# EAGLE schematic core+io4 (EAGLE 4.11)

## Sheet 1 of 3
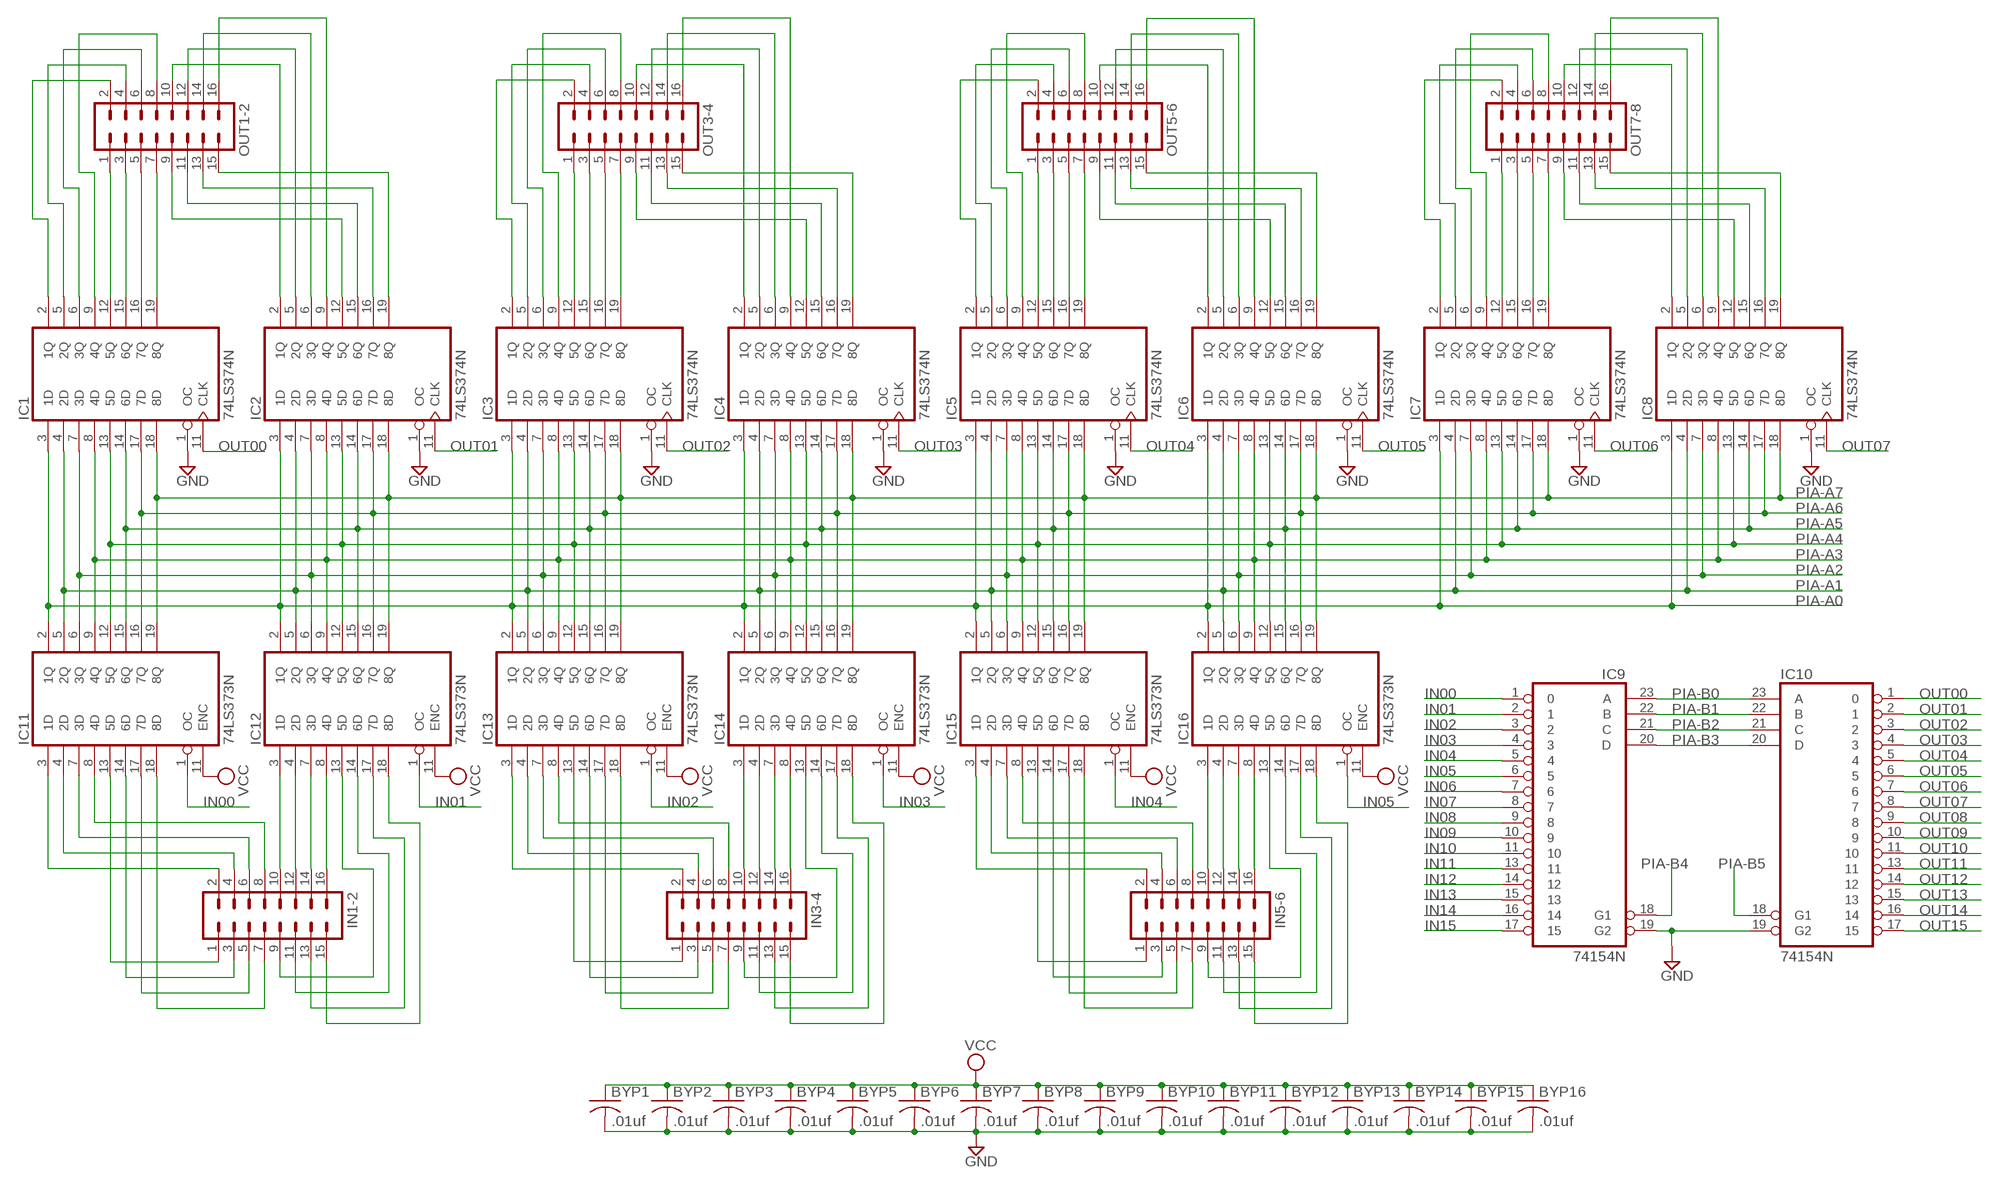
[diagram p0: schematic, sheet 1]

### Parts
BYP1  .01uf  C-US050-025X075  [C050-025X075]
BYP2  .01uf  C-US050-025X075  [C050-025X075]
BYP3  .01uf  C-US050-025X075  [C050-025X075]
BYP4  .01uf  C-US050-025X075  [C050-025X075]
BYP5  .01uf  C-US050-025X075  [C050-025X075]
BYP6  .01uf  C-US050-025X075  [C050-025X075]
BYP7  .01uf  C-US050-025X075  [C050-025X075]
BYP8  .01uf  C-US050-025X075  [C050-025X075]
BYP9  .01uf  C-US050-025X075  [C050-025X075]
BYP10  .01uf  C-US050-025X075  [C050-025X075]
BYP11  .01uf  C-US050-025X075  [C050-025X075]
BYP12  .01uf  C-US050-025X075  [C050-025X075]
BYP13  .01uf  C-US050-025X075  [C050-025X075]
BYP14  .01uf  C-US050-025X075  [C050-025X075]
BYP15  .01uf  C-US050-025X075  [C050-025X075]
BYP16  .01uf  C-US050-025X075  [C050-025X075]
IC1  74LS374N  [DIL20]
IC2  74LS374N  [DIL20]
IC3  74LS374N  [DIL20]
IC4  74LS374N  [DIL20]
IC5  74LS374N  [DIL20]
IC6  74LS374N  [DIL20]
IC7  74LS374N  [DIL20]
IC8  74LS374N  [DIL20]
IC9  74154N  [DIL24-6]
IC10  74154N  [DIL24-6]
IC11  74LS373N  [DIL20]
IC12  74LS373N  [DIL20]
IC13  74LS373N  [DIL20]
IC14  74LS373N  [DIL20]
IC15  74LS373N  [DIL20]
IC16  74LS373N  [DIL20]
IN1-2  MA08-2  [MA08-2]
IN3-4  MA08-2  [MA08-2]
IN5-6  MA08-2  [MA08-2]
OUT1-2  MA08-2  [MA08-2]
OUT3-4  MA08-2  [MA08-2]
OUT5-6  MA08-2  [MA08-2]
OUT7-8  MA08-2  [MA08-2]

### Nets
GND [Power]: BYP1.2 BYP2.2 BYP3.2 BYP4.2 BYP5.2 BYP6.2 BYP7.2 BYP8.2 BYP9.2 BYP10.2 BYP11.2 BYP12.2 BYP13.2 BYP14.2 BYP15.2 BYP16.2 IC1.1(OC) IC2.1(OC) IC3.1(OC) IC4.1(OC) IC5.1(OC) IC6.1(OC) IC7.1(OC) IC8.1(OC) IC9.19(G2) IC10.19(G2) ; also sheet 2,3
IN00: IC9.1 IC11.1(OC)
IN01: IC9.2 IC12.1(OC)
IN02: IC9.3 IC13.1(OC)
IN03: IC9.4 IC14.1(OC)
IN04: IC9.5 IC15.1(OC)
IN05: IC9.6 IC16.1(OC)
IN06: IC9.7
IN07: IC9.8
IN08: IC9.9
IN09: IC9.10
IN10: IC9.11
IN11: IC9.13
IN12: IC9.14
IN13: IC9.15
IN14: IC9.16
IN15: IC9.17
N$1: IC12.3(1D) IN1-2.10
N$2: IC12.4(2D) IN1-2.12
N$7: IC12.7(3D) IN1-2.14
N$8: IC12.8(4D) IN1-2.16
N$9: IC11.8(4D) IN1-2.8
N$10: IC11.7(3D) IN1-2.6
N$11: IC11.4(2D) IN1-2.4
N$12: IC11.3(1D) IN1-2.2
N$13: IC11.13(5D) IN1-2.1
N$14: IC11.14(6D) IN1-2.3
N$15: IC11.17(7D) IN1-2.5
N$16: IC11.18(8D) IN1-2.7
N$17: IC12.13(5D) IN1-2.9
N$18: IC12.14(6D) IN1-2.11
N$19: IC12.17(7D) IN1-2.13
N$20: IC12.18(8D) IN1-2.15
N$26: IC5.2(1Q) IC7.2(1Q) OUT5-6.2 OUT7-8.2
N$29: IC14.3(1D) IN3-4.10
N$30: IC14.4(2D) IN3-4.12
N$31: IC14.7(3D) IN3-4.14
N$32: IC14.8(4D) IN3-4.16
N$33: IC3.12(5Q) OUT3-4.1
N$34: IC3.15(6Q) OUT3-4.3
N$35: IC3.16(7Q) OUT3-4.5
N$36: IC3.19(8Q) OUT3-4.7
N$37: IC13.3(1D) IN3-4.2
N$38: IC13.4(2D) IN3-4.4
N$39: IC13.7(3D) IN3-4.6
N$40: IC13.8(4D) IN3-4.8
N$41: IC14.13(5D) IN3-4.9
N$42: IC14.14(6D) IN3-4.11
N$43: IC14.17(7D) IN3-4.13
N$44: IC14.18(8D) IN3-4.15
N$45: IC13.13(5D) IN3-4.1
N$46: IC13.14(6D) IN3-4.3
N$47: IC13.17(7D) IN3-4.5
N$48: IC13.18(8D) IN3-4.7
N$49: IC3.5(2Q) OUT3-4.4
N$50: IC3.6(3Q) OUT3-4.6
N$51: IC3.2(1Q) OUT3-4.2
N$52: IC3.9(4Q) OUT3-4.8
N$53: IC1.12(5Q) OUT1-2.1
N$54: IC1.15(6Q) OUT1-2.3
N$55: IC1.16(7Q) OUT1-2.5
N$56: IC1.19(8Q) OUT1-2.7
N$57: IC1.2(1Q) OUT1-2.2
N$58: IC1.5(2Q) OUT1-2.4
N$59: IC1.6(3Q) OUT1-2.6
N$60: IC1.9(4Q) OUT1-2.8
N$61: IC2.19(8Q) OUT1-2.15
N$62: IC2.16(7Q) OUT1-2.13
N$63: IC2.15(6Q) OUT1-2.11
N$64: IC2.12(5Q) OUT1-2.9
N$65: IC2.2(1Q) OUT1-2.10
N$66: IC2.5(2Q) OUT1-2.12
N$67: IC2.6(3Q) OUT1-2.14
N$68: IC2.9(4Q) OUT1-2.16
N$69: IC4.2(1Q) OUT3-4.10
N$70: IC4.5(2Q) OUT3-4.12
N$71: IC4.6(3Q) OUT3-4.14
N$72: IC4.9(4Q) OUT3-4.16
N$73: IC4.19(8Q) OUT3-4.15
N$74: IC4.16(7Q) OUT3-4.13
N$75: IC4.15(6Q) OUT3-4.11
N$76: IC4.12(5Q) OUT3-4.9
N$77: IC16.3(1D) IN5-6.10
N$78: IC16.4(2D) IN5-6.12
N$79: IC16.7(3D) IN5-6.14
N$80: IC16.8(4D) IN5-6.16
N$81: IC5.12(5Q) OUT5-6.1
N$82: IC5.15(6Q) OUT5-6.3
N$83: IC5.16(7Q) OUT5-6.5
N$84: IC5.19(8Q) OUT5-6.7
N$85: IC7.12(5Q) OUT7-8.1
N$86: IC7.15(6Q) OUT7-8.3
N$87: IC7.16(7Q) OUT7-8.5
N$88: IC7.19(8Q) OUT7-8.7
N$89: IC5.5(2Q) OUT5-6.4
N$90: IC5.6(3Q) OUT5-6.6
N$91: IC5.9(4Q) OUT5-6.8
N$92: IC6.12(5Q) OUT5-6.9
N$93: IC6.15(6Q) OUT5-6.11
N$95: IC6.16(7Q) OUT5-6.13
N$96: IC6.19(8Q) OUT5-6.15
N$97: IC6.2(1Q) OUT5-6.10
N$98: IC6.5(2Q) OUT5-6.12
N$99: IC6.6(3Q) OUT5-6.14
N$100: IC6.9(4Q) OUT5-6.16
N$101: IC15.3(1D) IN5-6.2
N$102: IC15.4(2D) IN5-6.4
N$103: IC15.7(3D) IN5-6.6
N$104: IC15.8(4D) IN5-6.8
N$105: IC16.13(5D) IN5-6.9
N$106: IC16.14(6D) IN5-6.11
N$107: IC16.17(7D) IN5-6.13
N$108: IC16.18(8D) IN5-6.15
N$109: IC15.13(5D) IN5-6.1
N$110: IC15.14(6D) IN5-6.3
N$111: IC15.17(7D) IN5-6.5
N$112: IC15.18(8D) IN5-6.7
N$113: IC8.19(8Q) OUT7-8.15
N$114: IC8.16(7Q) OUT7-8.13
N$115: IC8.15(6Q) OUT7-8.11
N$116: IC8.12(5Q) OUT7-8.9
N$117: IC8.2(1Q) OUT7-8.10
N$118: IC8.5(2Q) OUT7-8.12
N$119: IC8.6(3Q) OUT7-8.14
N$120: IC8.9(4Q) OUT7-8.16
N$121: IC7.9(4Q) OUT7-8.8
N$122: IC7.6(3Q) OUT7-8.6
N$123: IC7.5(2Q) OUT7-8.4
OUT00: IC1.11(CLK) IC10.1
OUT01: IC2.11(CLK) IC10.2
OUT02: IC3.11(CLK) IC10.3
OUT03: IC4.11(CLK) IC10.4
OUT04: IC5.11(CLK) IC10.5
OUT05: IC6.11(CLK) IC10.6
OUT06: IC7.11(CLK) IC10.7
OUT07: IC8.11(CLK) IC10.8
OUT08: IC10.9
OUT09: IC10.10
OUT10: IC10.11
OUT11: IC10.13
OUT12: IC10.14
OUT13: IC10.15
OUT14: IC10.16
OUT15: IC10.17
PIA-A0: IC1.3(1D) IC2.3(1D) IC3.3(1D) IC4.3(1D) IC5.3(1D) IC6.3(1D) IC7.3(1D) IC8.3(1D) IC11.2(1Q) IC12.2(1Q) IC13.2(1Q) IC14.2(1Q) IC15.2(1Q) IC16.2(1Q) ; also sheet 2,3
PIA-A1: IC1.4(2D) IC2.4(2D) IC3.4(2D) IC4.4(2D) IC5.4(2D) IC6.4(2D) IC7.4(2D) IC8.4(2D) IC11.5(2Q) IC12.5(2Q) IC13.5(2Q) IC14.5(2Q) IC15.5(2Q) IC16.5(2Q) ; also sheet 2,3
PIA-A2: IC1.7(3D) IC2.7(3D) IC3.7(3D) IC4.7(3D) IC5.7(3D) IC6.7(3D) IC7.7(3D) IC8.7(3D) IC11.6(3Q) IC12.6(3Q) IC13.6(3Q) IC14.6(3Q) IC15.6(3Q) IC16.6(3Q) ; also sheet 2,3
PIA-A3: IC1.8(4D) IC2.8(4D) IC3.8(4D) IC4.8(4D) IC5.8(4D) IC6.8(4D) IC7.8(4D) IC8.8(4D) IC11.9(4Q) IC12.9(4Q) IC13.9(4Q) IC14.9(4Q) IC15.9(4Q) IC16.9(4Q) ; also sheet 2,3
PIA-A4: IC1.13(5D) IC2.13(5D) IC3.13(5D) IC4.13(5D) IC5.13(5D) IC6.13(5D) IC7.13(5D) IC8.13(5D) IC11.12(5Q) IC12.12(5Q) IC13.12(5Q) IC14.12(5Q) IC15.12(5Q) IC16.12(5Q) ; also sheet 2,3
PIA-A5: IC1.14(6D) IC2.14(6D) IC3.14(6D) IC4.14(6D) IC5.14(6D) IC6.14(6D) IC7.14(6D) IC8.14(6D) IC11.15(6Q) IC12.15(6Q) IC13.15(6Q) IC14.15(6Q) IC15.15(6Q) IC16.15(6Q) ; also sheet 2,3
PIA-A6: IC1.17(7D) IC2.17(7D) IC3.17(7D) IC4.17(7D) IC5.17(7D) IC6.17(7D) IC7.17(7D) IC8.17(7D) IC11.16(7Q) IC12.16(7Q) IC13.16(7Q) IC14.16(7Q) IC15.16(7Q) IC16.16(7Q) ; also sheet 2,3
PIA-A7: IC1.18(8D) IC2.18(8D) IC3.18(8D) IC4.18(8D) IC5.18(8D) IC6.18(8D) IC7.18(8D) IC8.18(8D) IC11.19(8Q) IC12.19(8Q) IC13.19(8Q) IC14.19(8Q) IC15.19(8Q) IC16.19(8Q) ; also sheet 2,3
PIA-B0: IC9.23(A) IC10.23(A) ; also sheet 2,3
PIA-B1: IC9.22(B) IC10.22(B) ; also sheet 2,3
PIA-B2: IC9.21(C) IC10.21(C) ; also sheet 2,3
PIA-B3: IC9.20(D) IC10.20(D) ; also sheet 2,3
PIA-B4: IC9.18(G1) ; also sheet 2,3
PIA-B5: IC10.18(G1) ; also sheet 2,3
VCC [Power]: BYP1.1 BYP2.1 BYP3.1 BYP4.1 BYP5.1 BYP6.1 BYP7.1 BYP8.1 BYP9.1 BYP10.1 BYP11.1 BYP12.1 BYP13.1 BYP14.1 BYP15.1 BYP16.1 IC11.11(ENC) IC12.11(ENC) IC13.11(ENC) IC14.11(ENC) IC15.11(ENC) IC16.11(ENC) ; also sheet 2,3

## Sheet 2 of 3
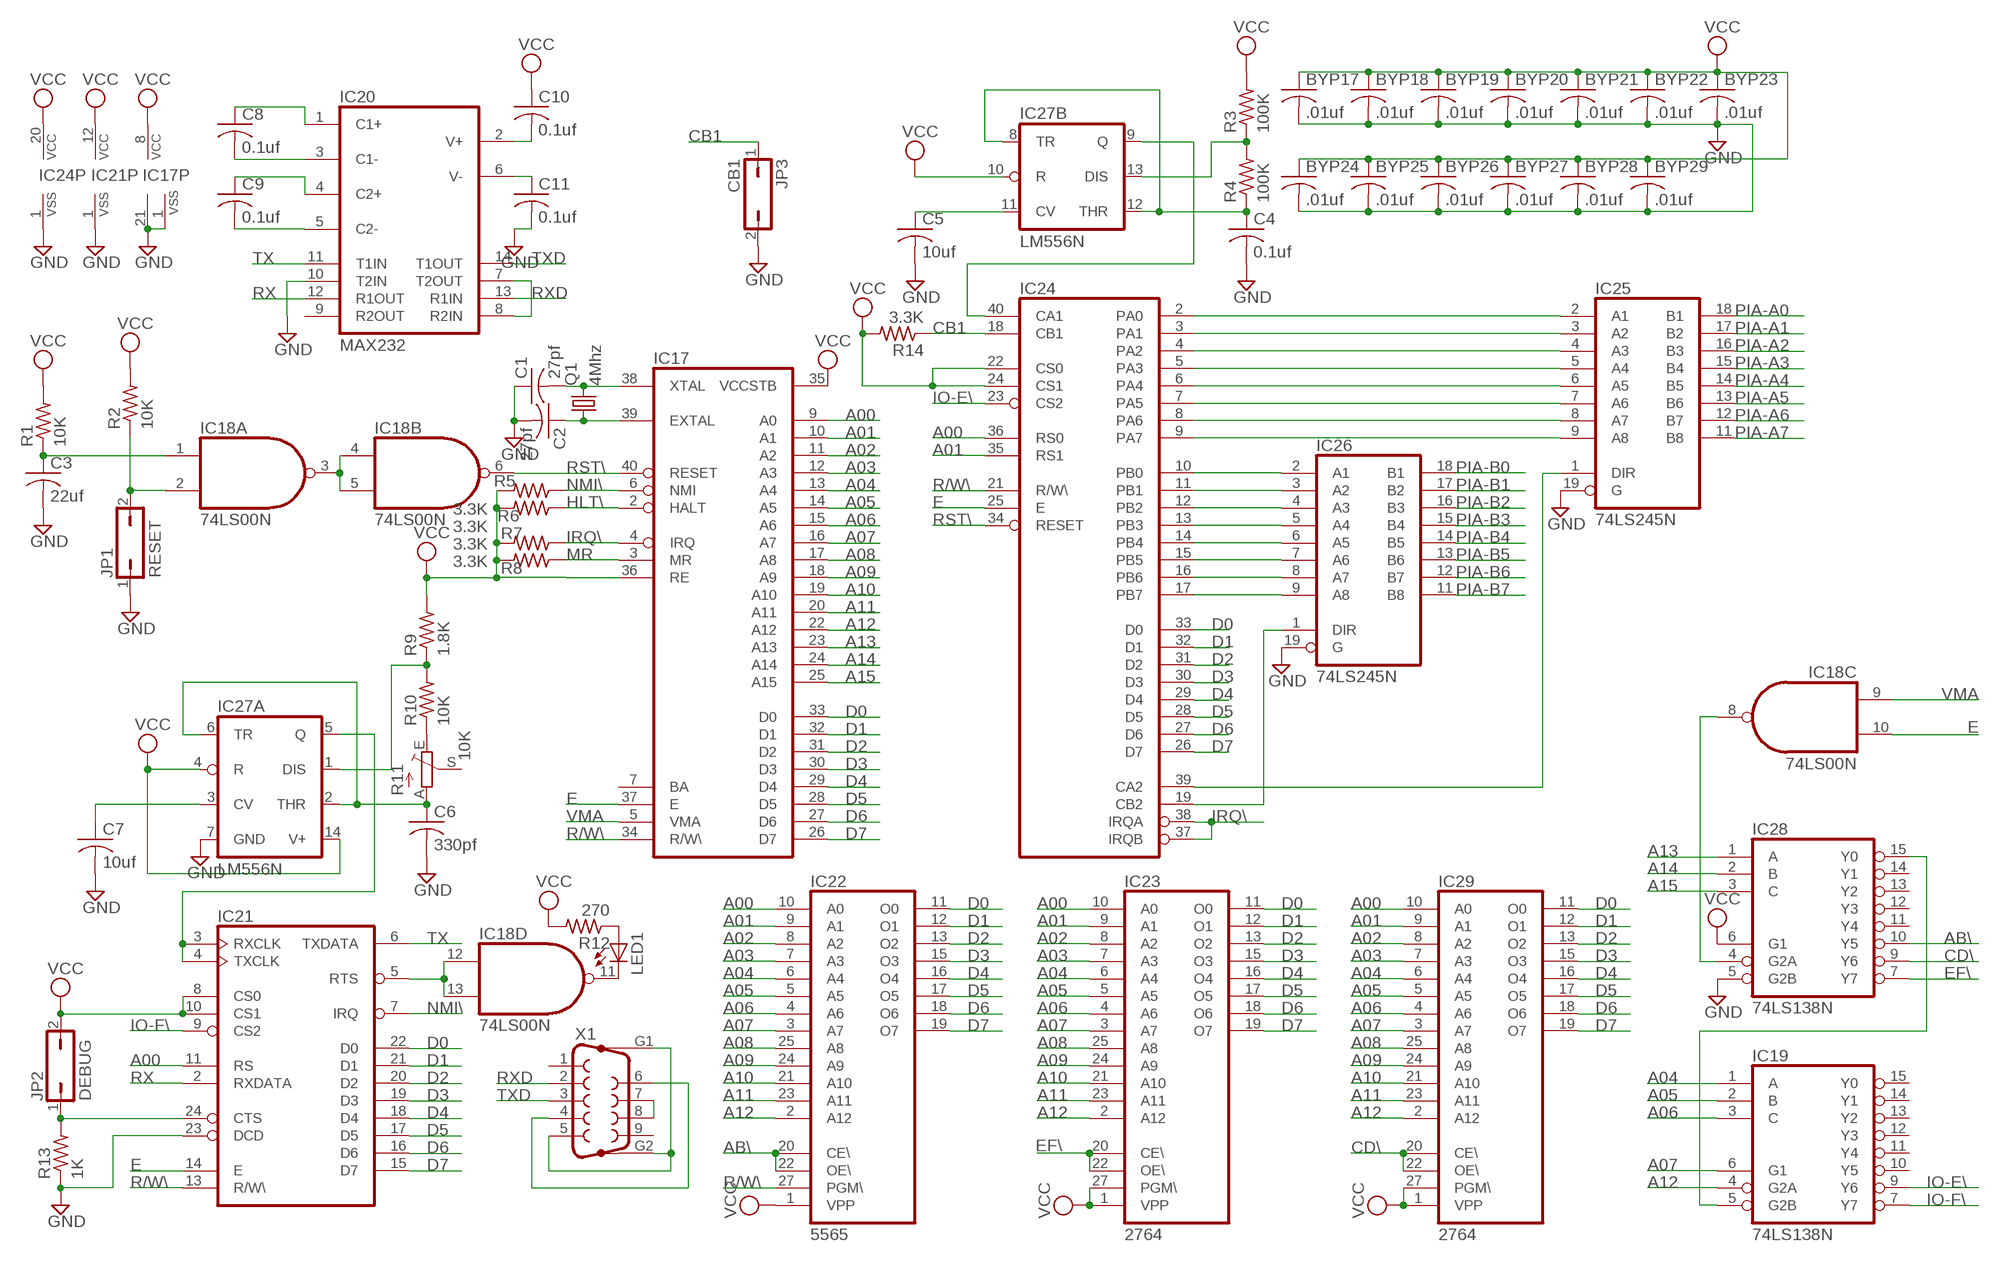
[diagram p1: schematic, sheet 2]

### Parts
BYP17  .01uf  C-US050-025X075  [C050-025X075]
BYP18  .01uf  C-US050-025X075  [C050-025X075]
BYP19  .01uf  C-US050-025X075  [C050-025X075]
BYP20  .01uf  C-US050-025X075  [C050-025X075]
BYP21  .01uf  C-US050-025X075  [C050-025X075]
BYP22  .01uf  C-US050-025X075  [C050-025X075]
BYP23  .01uf  C-US050-025X075  [C050-025X075]
BYP24  .01uf  C-US050-025X075  [C050-025X075]
BYP25  .01uf  C-US050-025X075  [C050-025X075]
BYP26  .01uf  C-US050-025X075  [C050-025X075]
BYP27  .01uf  C-US050-025X075  [C050-025X075]
BYP28  .01uf  C-US050-025X075  [C050-025X075]
BYP29  .01uf  C-US050-025X075  [C050-025X075]
C1  27pf  C-US050-025X075  [C050-025X075]
C2  27pf  C-US050-025X075  [C050-025X075]
C3  22uf  C-US102-043X133  [C102-043X133]
C4  0.1uf  C-US050-025X075  [C050-025X075]
C5  10uf  C-US050-025X075  [C050-025X075]
C6  330pf  C-US050-025X075  [C050-025X075]
C7  10uf  C-US050-025X075  [C050-025X075]
C8  0.1uf  C-US050-025X075  [C050-025X075]
C9  0.1uf  C-US050-025X075  [C050-025X075]
C10  0.1uf  C-US050-025X075  [C050-025X075]
C11  0.1uf  C-US050-025X075  [C050-025X075]
IC17  6802  [DIL40]
IC18  74LS00N  [DIL14]
IC19  74LS138N  [DIL16]
IC20  MAX232  [DIL16]
IC21  6850  [DIL24]
IC22  5565  2764  [DIL28]
IC23  2764  [DIL28]
IC24  6821  [DIL40]
IC25  74LS245N  [DIL20]
IC26  74LS245N  [DIL20]
IC27  LM556N  [DIL14]
IC28  74LS138N  [DIL16]
IC29  2764  [DIL28]
JP1  RESET  JP1Q  [JP1]
JP2  DEBUG  JP1Q  [JP1]
JP3  CB1  JP1Q  [JP1]
LED1  LED3MM  [LED3MM]
Q1  4Mhz  CRYTALHC18U-V  [HC18U-V]
R1  10K  R-US_0207/7  [0207/7]
R2  10K  R-US_0207/7  [0207/7]
R3  100K  R-US_0207/7  [0207/7]
R4  100K  R-US_0207/7  [0207/7]
R5  3.3K  R-US_0207/7  [0207/7]
R6  3.3K  R-US_0207/7  [0207/7]
R7  3.3K  R-US_0207/7  [0207/7]
R8  3.3K  R-US_0207/7  [0207/7]
R9  1.8K  R-US_0207/7  [0207/7]
R10  10K  R-US_0207/7  [0207/7]
R11  10K  TRIM_EU-B90P  [SP19L]
R12  270  R-US_0207/7  [0207/7]
R13  1K  R-US_0207/7  [0207/7]
R14  3.3K  R-US_0207/7  [0207/7]
X1  F09HP  [F09HP]

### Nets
A00: IC17.9(A0) IC21.11(RS) IC22.10(A0) IC23.10(A0) IC24.36(RS0) IC29.10(A0)
A01: IC17.10(A1) IC22.9(A1) IC23.9(A1) IC24.35(RS1) IC29.9(A1)
A02: IC17.11(A2) IC22.8(A2) IC23.8(A2) IC29.8(A2)
A03: IC17.12(A3) IC22.7(A3) IC23.7(A3) IC29.7(A3)
A04: IC17.13(A4) IC19.1(A) IC22.6(A4) IC23.6(A4) IC29.6(A4)
A05: IC17.14(A5) IC19.2(B) IC22.5(A5) IC23.5(A5) IC29.5(A5)
A06: IC17.15(A6) IC19.3(C) IC22.4(A6) IC23.4(A6) IC29.4(A6)
A07: IC17.16(A7) IC19.6(G1) IC22.3(A7) IC23.3(A7) IC29.3(A7)
A08: IC17.17(A8) IC22.25(A8) IC23.25(A8) IC29.25(A8)
A09: IC17.18(A9) IC22.24(A9) IC23.24(A9) IC29.24(A9)
A10: IC17.19(A10) IC22.21(A10) IC23.21(A10) IC29.21(A10)
A11: IC17.20(A11) IC22.23(A11) IC23.23(A11) IC29.23(A11)
A12: IC17.22(A12) IC19.4(G2A) IC22.2(A12) IC23.2(A12) IC29.2(A12)
A13: IC17.23(A13) IC28.1(A)
A14: IC17.24(A14) IC28.2(B)
A15: IC17.25(A15) IC28.3(C)
AB\: IC22.20(CE\) IC22.22(OE\) IC28.10(Y5)
CB1: IC24.18(CB1) JP3.1 R14.1
CD\: IC28.9(Y6) IC29.20(CE\) IC29.22(OE\)
D0: IC17.33(D0) IC21.22(D0) IC22.11(O0) IC23.11(O0) IC24.33(D0) IC29.11(O0)
D1: IC17.32(D1) IC21.21(D1) IC22.12(O1) IC23.12(O1) IC24.32(D1) IC29.12(O1)
D2: IC17.31(D2) IC21.20(D2) IC22.13(O2) IC23.13(O2) IC24.31(D2) IC29.13(O2)
D3: IC17.30(D3) IC21.19(D3) IC22.15(O3) IC23.15(O3) IC24.30(D3) IC29.15(O3)
D4: IC17.29(D4) IC21.18(D4) IC22.16(O4) IC23.16(O4) IC24.29(D4) IC29.16(O4)
D5: IC17.28(D5) IC21.17(D5) IC22.17(O5) IC23.17(O5) IC24.28(D5) IC29.17(O5)
D6: IC17.27(D6) IC21.16(D6) IC22.18(O6) IC23.18(O6) IC24.27(D6) IC29.18(O6)
D7: IC17.26(D7) IC21.15(D7) IC22.19(O7) IC23.19(O7) IC24.26(D7) IC29.19(O7)
E: IC17.37(E) IC18.10(C:I1) IC21.14(E) IC24.25(E)
EF\: IC23.20(CE\) IC23.22(OE\) IC28.7(Y7)
GND [Power]: BYP17.2 BYP18.2 BYP19.2 BYP20.2 BYP21.2 BYP22.2 BYP23.2 BYP24.2 BYP25.2 BYP26.2 BYP27.2 BYP28.2 BYP29.2 C1.1 C2.2 C3.2 C4.2 C5.2 C6.2 C7.2 C11.2 IC17.1(VSS) IC17.21(VSS) IC20.10(T2IN) IC21.1(VSS) IC21.23(DCD) IC24.1(VSS) IC25.19(G) IC26.19(G) IC27.7(A:GND) IC28.5(G2B) JP1.1 JP3.2 R13.1 ; also sheet 1,3
HLT\: IC17.2(HALT) R5.1
IO-E\: IC19.9(Y6) IC24.23(CS2)
IO-F\: IC19.7(Y7) IC21.9(CS2)
IRQ\: IC17.4(IRQ) IC24.37(IRQB) IC24.38(IRQA) R7.1
MR: IC17.3(MR) R8.1
N$3: C2.1 IC17.39(EXTAL) Q1.1
N$4: C1.2 IC17.38(XTAL) Q1.2
N$5: IC24.2(PA0) IC25.2(A1)
N$6: IC18.3(A:O) IC18.4(B:I0) IC18.5(B:I1)
N$21: C3.1 IC18.1(A:I0) R1.1
N$22: IC18.2(A:I1) JP1.2 R2.1
N$23: IC21.3(RXCLK) IC21.4(TXCLK) IC27.5(A:Q)
N$24: IC24.10(PB0) IC26.2(A1)
N$25: IC24.11(PB1) IC26.3(A2)
N$27: C6.1 IC27.2(A:THR) IC27.6(A:TR) R11.A
N$28: IC27.1(A:DIS) R9.1 R10.2
N$94: IC24.12(PB2) IC26.4(A3)
N$124: IC24.13(PB3) IC26.5(A4)
N$125: IC24.14(PB4) IC26.6(A5)
N$126: IC24.15(PB5) IC26.7(A6)
N$127: IC24.16(PB6) IC26.8(A7)
N$128: IC24.17(PB7) IC26.9(A8)
N$129: IC24.3(PA1) IC25.3(A2)
N$130: IC24.4(PA2) IC25.4(A3)
N$131: IC24.5(PA3) IC25.5(A4)
N$132: IC24.6(PA4) IC25.6(A5)
N$133: IC24.7(PA5) IC25.7(A6)
N$134: IC24.8(PA6) IC25.8(A7)
N$135: IC24.9(PA7) IC25.9(A8)
N$136: IC24.19(CB2) IC26.1(DIR)
N$137: IC24.39(CA2) IC25.1(DIR)
N$138: IC24.40(CA1) IC27.9(B:Q)
N$140: C4.1 IC27.8(B:TR) IC27.12(B:THR) R4.1
N$141: IC27.13(B:DIS) R3.1 R4.2
N$142: C5.1 IC27.11(B:CV)
N$143: R10.1 R11.E
N$144: X1.4 X1.6
N$145: X1.7 X1.8
N$146: X1.5 X1.G1 X1.G2
N$147: IC18.12(D:I0) IC18.13(D:I1) IC21.5(RTS)
N$148: IC18.11(D:O) LED1.K(C)
N$149: LED1.A R12.1
N$150: IC21.24(CTS) JP2.1 R13.2
N$151: IC18.8(C:O) IC28.4(G2A)
N$152: IC19.5(G2B) IC28.15(Y0)
N$153: IC20.7(T2OUT) IC20.8(R2IN)
N$154: C7.1 IC27.3(A:CV)
N$155: C9.2 IC20.5(C2-)
N$156: C9.1 IC20.4(C2+)
N$157: C8.2 IC20.3(C1-)
N$158: C8.1 IC20.1(C1+)
N$159: C11.1 IC20.6(V-)
N$160: C10.2 IC20.2(V+)
NMI\: IC17.6(NMI) IC21.7(IRQ) R6.1
PIA-A0: IC25.18(B1) ; also sheet 1,3
PIA-A1: IC25.17(B2) ; also sheet 1,3
PIA-A2: IC25.16(B3) ; also sheet 1,3
PIA-A3: IC25.15(B4) ; also sheet 1,3
PIA-A4: IC25.14(B5) ; also sheet 1,3
PIA-A5: IC25.13(B6) ; also sheet 1,3
PIA-A6: IC25.12(B7) ; also sheet 1,3
PIA-A7: IC25.11(B8) ; also sheet 1,3
PIA-B0: IC26.18(B1) ; also sheet 1,3
PIA-B1: IC26.17(B2) ; also sheet 1,3
PIA-B2: IC26.16(B3) ; also sheet 1,3
PIA-B3: IC26.15(B4) ; also sheet 1,3
PIA-B4: IC26.14(B5) ; also sheet 1,3
PIA-B5: IC26.13(B6) ; also sheet 1,3
PIA-B6: IC26.12(B7) ; also sheet 3
PIA-B7: IC26.11(B8) ; also sheet 3
R/W\: IC17.34(R/W\) IC21.13(R/W\) IC22.27(PGM\) IC24.21(R/W\)
RST\: IC17.40(RESET) IC18.6(B:O) IC24.34(RESET)
RX: IC20.12(R1OUT) IC21.2(RXDATA)
RXD: IC20.13(R1IN) X1.2
TX: IC20.11(T1IN) IC21.6(TXDATA)
TXD: IC20.14(T1OUT) X1.3
VCC [Power]: BYP17.1 BYP18.1 BYP19.1 BYP20.1 BYP21.1 BYP22.1 BYP23.1 BYP24.1 BYP25.1 BYP26.1 BYP27.1 BYP28.1 BYP29.1 C10.1 IC17.8(VCC) IC17.35(VCCSTB) IC17.36(RE) IC21.8(CS0) IC21.10(CS1) IC21.12(VCC) IC22.1(VPP) IC23.1(VPP) IC23.27(PGM\) IC24.20(VCC) IC24.22(CS0) IC24.24(CS1) IC27.4(A:R) IC27.10(B:R) IC27.14(A:V+) IC28.6(G1) IC29.1(VPP) IC29.27(PGM\) JP2.2 R1.2 R2.2 R3.2 R5.2 R6.2 R7.2 R8.2 R9.2 R12.2 R14.2 ; also sheet 1,3
VMA: IC17.5(VMA) IC18.9(C:I0)
Unconnected: IC17.7(BA) IC19.10(Y5) IC19.11(Y4) IC19.12(Y3) IC19.13(Y2) IC19.14(Y1) IC19.15(Y0) IC20.9(R2OUT) IC28.11(Y4) IC28.12(Y3) IC28.13(Y2) IC28.14(Y1) R11.S X1.1 X1.9

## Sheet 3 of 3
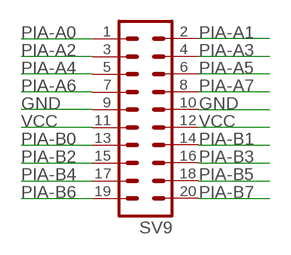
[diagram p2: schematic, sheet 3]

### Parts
SV9  MA10-2  [MA10-2]

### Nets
GND [Power]: SV9.9 SV9.10 ; also sheet 1,2
PIA-A0: SV9.1 ; also sheet 1,2
PIA-A1: SV9.2 ; also sheet 1,2
PIA-A2: SV9.3 ; also sheet 1,2
PIA-A3: SV9.4 ; also sheet 1,2
PIA-A4: SV9.5 ; also sheet 1,2
PIA-A5: SV9.6 ; also sheet 1,2
PIA-A6: SV9.7 ; also sheet 1,2
PIA-A7: SV9.8 ; also sheet 1,2
PIA-B0: SV9.13 ; also sheet 1,2
PIA-B1: SV9.14 ; also sheet 1,2
PIA-B2: SV9.15 ; also sheet 1,2
PIA-B3: SV9.16 ; also sheet 1,2
PIA-B4: SV9.17 ; also sheet 1,2
PIA-B5: SV9.18 ; also sheet 1,2
PIA-B6: SV9.19 ; also sheet 2
PIA-B7: SV9.20 ; also sheet 2
VCC [Power]: SV9.11 SV9.12 ; also sheet 1,2

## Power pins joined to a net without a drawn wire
GND: IC1.10(GND) IC2.10(GND) IC3.10(GND) IC4.10(GND) IC5.10(GND) IC6.10(GND) IC7.10(GND) IC8.10(GND) IC9.12(GND) IC10.12(GND) IC11.10(GND) IC12.10(GND) IC13.10(GND) IC14.10(GND) IC15.10(GND) IC16.10(GND) IC18.7(P:GND) IC19.8(GND) IC20.15(GND) IC22.14(GND) IC23.14(GND) IC25.10(GND) IC26.10(GND) IC28.8(GND) IC29.14(GND)
VCC: IC1.20(VCC) IC2.20(VCC) IC3.20(VCC) IC4.20(VCC) IC5.20(VCC) IC6.20(VCC) IC7.20(VCC) IC8.20(VCC) IC9.24(VCC) IC10.24(VCC) IC11.20(VCC) IC12.20(VCC) IC13.20(VCC) IC14.20(VCC) IC15.20(VCC) IC16.20(VCC) IC18.14(P:VCC) IC19.16(VCC) IC20.16(VCC) IC22.28(VCC) IC23.28(VCC) IC25.20(VCC) IC26.20(VCC) IC28.16(VCC) IC29.28(VCC)

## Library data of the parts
BYP1-BYP29 C1-C11 = rcl:C-US: CAPACITOR, American symbol
IC1-IC8 = 74xx-us:74*374: Octal D type transparent LATCH, edge triggered
IC9 IC10 = 74xx-us:74*154: 4-line to 16-line data SELECTOR/MULTIPLEXER
IC11-IC16 = 74xx-us:74*373: Octal D type transparent LATCH, edge triggered
IC17 = micro-motorola:6802: MICROCONTROLLER/MEMORY DEVICE
IC18 = 74xx-us:74*00: Quad 2-input NAND gate
IC19 IC28 = 74xx-us:74*138: 3-line to 8-line DECODER/DEMULTIPLEXER
IC20 = maxim:MAX232: RS232 TRANSEIVER
IC21 = micro-motorola:6850: MICROCONTROLLER/MEMORY DEVICE
IC22 IC23 IC29 = memory:2764: MEMORY
IC24 = micro-motorola:6821: MICROCONTROLLER/MEMORY DEVICE
IC25 IC26 = 74xx-us:74*245: Octal BUS TRANSCEIVER, 3-state
IC27 = linear:*556: Dual TIMER
IN1-2 IN3-4 IN5-6 OUT1-2 OUT3-4 OUT5-6 OUT7-8 = con-lstb:MA08-2: PIN HEADER
JP1-JP3 = jumper:JP1Q: JUMPER
LED1 = led:LED: LED
Q1 = crystal:CRYTAL: CRYSTAL
R1-R10 R12-R14 = rcl:R-US_: RESISTOR, American symbol
R11 = pot:TRIM_EU-: POTENTIOMETER
SV9 = con-lstb:MA10-2: PIN HEADER
X1 = con-subd:F09HP: SUB-D

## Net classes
1 Power: width 0.508 mm, drill 0.254 mm, clearance 0.254 mm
